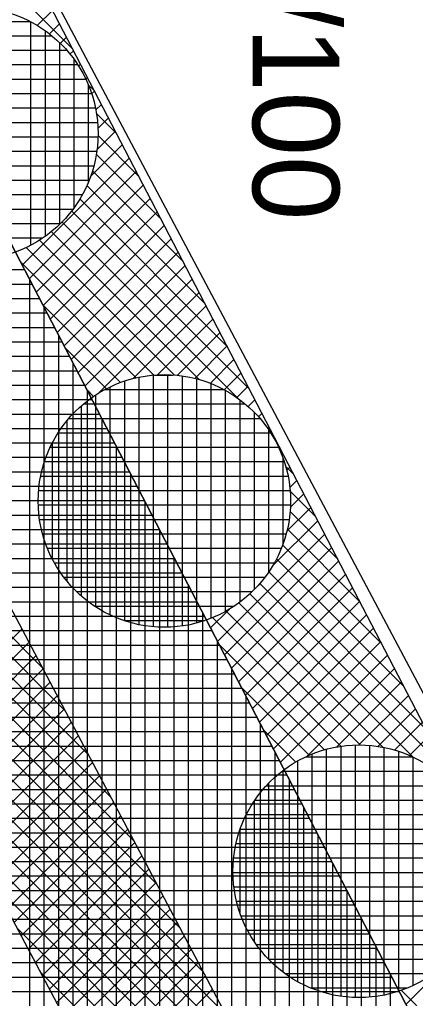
# Model space of a CAD drawing. Extents: x -565346 to -564154, y -1097386 to -1095620.
# Drawn here: x -564305.27 to -564299.78, y -1096071.21 to -1096057.65 of the extents above; entities that cross this region are included whole.
import ezdxf

# ---------------------------------------------------------------- set-up
doc = ezdxf.new("R2010")
doc.units = 0
for name, color, linetype in [('Vrstva 13', 7, 'Continuous'), ('Vrstva 40', 7, 'Continuous'), ('Vrstva 41', 7, 'Continuous'), ('Vrstva 42', 7, 'Continuous'), ('Vrstva 43', 7, 'Continuous'), ('Vrstva 44', 7, 'Continuous')]:
    doc.layers.add(name, color=color, linetype=linetype)

msp = doc.modelspace()

# ---------------------------------------------------------------- linework, layer by layer
at = {"layer": 'Vrstva 13'}
msp.add_line((-564310.36, -1096046.86), (-564292.41, -1096080.67), dxfattribs=at)
at = {"layer": 'Vrstva 41'}
msp.add_lwpolyline([(-564317.9, -1095918.68), (-564319.837, -1095918.359), (-564322.792, -1095953.471), (-564316.779, -1095990.732), (-564317.708, -1096006.365), (-564312.296, -1096047.478), (-564277.924, -1096113.563), (-564240.773, -1096165.119), (-564207.452, -1096208.029), (-564205.9, -1096206.84), (-564239.15, -1096163.95), (-564276.21, -1096112.52), (-564310.36, -1096046.86), (-564315.7, -1096006.29), (-564314.77, -1095990.63), (-564320.6, -1095954.5), (-564320.51, -1095950.21)], close=True, dxfattribs=at)
at = {"layer": 'Vrstva 42'}
for p, q in [((-564307.288, -1096055.299), (-564304.543, -1096058.045)), ((-564304.816, -1096057.519), (-564305.027, -1096057.729)), ((-564304.72, -1096057.705), (-564304.86, -1096057.845)), ((-564304.623, -1096057.891), (-564304.71, -1096057.977)), ((-564304.526, -1096058.077), (-564304.575, -1096058.126)), ((-564304.429, -1096058.263), (-564304.456, -1096058.29)), ((-564304.333, -1096058.449), (-564304.355, -1096058.472)), ((-564304.321, -1096058.55), (-564304.236, -1096058.634)), ((-564304.236, -1096058.635), (-564304.274, -1096058.673)), ((-564304.139, -1096058.821), (-564304.216, -1096058.898)), ((-564304.209, -1096058.944), (-564303.93, -1096059.223)), ((-564304.042, -1096059.007), (-564304.188, -1096059.153)), ((-564303.945, -1096059.193), (-564304.2, -1096059.448)), ((-564304.185, -1096059.251), (-564303.623, -1096059.813)), ((-564303.849, -1096059.379), (-564304.292, -1096059.823)), ((-564303.752, -1096059.565), (-564305.237, -1096061.05)), ((-564304.21, -1096059.509), (-564303.317, -1096060.402)), ((-564304.263, -1096059.739), (-564303.01, -1096060.992)), ((-564303.655, -1096059.751), (-564305.14, -1096061.236)), ((-564303.558, -1096059.938), (-564305.043, -1096061.422)), ((-564304.34, -1096059.945), (-564302.704, -1096061.581)), ((-564303.462, -1096060.124), (-564304.946, -1096061.608)), ((-564304.438, -1096060.13), (-564302.397, -1096062.17)), ((-564303.365, -1096060.31), (-564304.85, -1096061.795)), ((-564304.554, -1096060.297), (-564302.091, -1096062.76)), ((-564303.268, -1096060.496), (-564304.753, -1096061.981)), ((-564304.686, -1096060.447), (-564302.235, -1096062.898)), ((-564304.834, -1096060.582), (-564302.782, -1096062.634)), ((-564303.171, -1096060.682), (-564304.656, -1096062.167)), ((-564305.18, -1096060.802), (-564303.41, -1096062.572)), ((-564304.998, -1096060.701), (-564303.127, -1096062.571)), ((-564303.074, -1096060.868), (-564304.559, -1096062.353)), ((-564305.261, -1096061.003), (-564303.655, -1096062.609)), ((-564302.978, -1096061.054), (-564304.463, -1096062.539)), ((-564302.881, -1096061.24), (-564304.366, -1096062.725)), ((-564302.784, -1096061.426), (-564304.188, -1096062.83)), ((-564304.955, -1096061.592), (-564303.872, -1096062.675)), ((-564302.687, -1096061.612), (-564303.696, -1096062.62)), ((-564309.792, -1096061.789), (-564304.965, -1096066.616)), ((-564302.591, -1096061.798), (-564303.362, -1096062.569)), ((-564302.494, -1096061.984), (-564303.083, -1096062.574)), ((-564304.648, -1096062.182), (-564304.068, -1096062.762)), ((-564302.397, -1096062.17), (-564302.844, -1096062.617)), ((-564309.472, -1096062.392), (-564304.645, -1096067.218)), ((-564302.3, -1096062.356), (-564302.629, -1096062.686)), ((-564302.203, -1096062.542), (-564302.435, -1096062.774)), ((-564304.342, -1096062.771), (-564304.246, -1096062.867)), ((-564302.107, -1096062.729), (-564302.26, -1096062.882)), ((-564309.152, -1096062.995), (-564304.325, -1096067.821)), ((-564302.01, -1096062.915), (-564302.102, -1096063.007)), ((-564301.913, -1096063.101), (-564301.96, -1096063.148)), ((-564301.848, -1096063.285), (-564301.784, -1096063.349)), ((-564301.816, -1096063.287), (-564301.835, -1096063.305)), ((-564301.72, -1096063.473), (-564301.727, -1096063.48)), ((-564308.832, -1096063.598), (-564304.005, -1096068.424)), ((-564301.623, -1096063.659), (-564301.638, -1096063.674)), ((-564301.584, -1096063.832), (-564301.477, -1096063.938)), ((-564301.526, -1096063.845), (-564301.569, -1096063.888)), ((-564301.429, -1096064.031), (-564301.525, -1096064.126)), ((-564308.512, -1096064.201), (-564303.685, -1096069.027)), ((-564301.521, -1096064.177), (-564301.171, -1096064.528)), ((-564301.333, -1096064.217), (-564301.519, -1096064.403)), ((-564301.236, -1096064.403), (-564301.567, -1096064.735)), ((-564301.522, -1096064.46), (-564300.864, -1096065.117)), ((-564301.139, -1096064.589), (-564301.765, -1096065.215)), ((-564301.559, -1096064.705), (-564300.558, -1096065.707)), ((-564308.192, -1096064.804), (-564303.365, -1096069.63)), ((-564301.042, -1096064.775), (-564302.527, -1096066.26)), ((-564300.945, -1096064.961), (-564302.43, -1096066.446)), ((-564301.625, -1096064.922), (-564300.251, -1096066.296)), ((-564300.849, -1096065.147), (-564302.334, -1096066.632)), ((-564301.712, -1096065.118), (-564299.945, -1096066.885)), ((-564301.817, -1096065.296), (-564299.638, -1096067.475)), ((-564307.872, -1096065.407), (-564303.045, -1096070.233)), ((-564300.752, -1096065.333), (-564302.237, -1096066.818)), ((-564300.655, -1096065.52), (-564302.14, -1096067.004)), ((-564301.94, -1096065.456), (-564299.332, -1096068.064)), ((-564302.079, -1096065.6), (-564299.815, -1096067.864)), ((-564300.558, -1096065.706), (-564302.043, -1096067.19)), ((-564302.363, -1096065.813), (-564302.624, -1096066.074)), ((-564302.406, -1096065.839), (-564300.55, -1096067.695)), ((-564302.233, -1096065.728), (-564300.235, -1096067.727)), ((-564302.597, -1096065.93), (-564300.813, -1096067.714)), ((-564300.462, -1096065.892), (-564301.946, -1096067.377)), ((-564307.551, -1096066.009), (-564302.725, -1096070.836)), ((-564305.244, -1096066.091), (-564306.723, -1096067.57)), ((-564300.365, -1096066.078), (-564301.85, -1096067.563)), ((-564305.146, -1096066.275), (-564306.625, -1096067.754)), ((-564302.502, -1096066.308), (-564301.046, -1096067.764)), ((-564300.268, -1096066.264), (-564301.753, -1096067.749)), ((-564305.048, -1096066.46), (-564306.527, -1096067.939)), ((-564300.171, -1096066.45), (-564301.656, -1096067.935)), ((-564307.231, -1096066.612), (-564302.405, -1096071.439)), ((-564304.95, -1096066.645), (-564306.429, -1096068.124)), ((-564300.074, -1096066.636), (-564301.291, -1096067.853)), ((-564304.852, -1096066.83), (-564306.331, -1096068.309)), ((-564302.196, -1096066.897), (-564301.256, -1096067.837)), ((-564299.978, -1096066.822), (-564300.88, -1096067.725)), ((-564304.754, -1096067.014), (-564306.233, -1096068.493)), ((-564299.881, -1096067.008), (-564300.567, -1096067.694)), ((-564304.656, -1096067.199), (-564306.135, -1096068.678)), ((-564299.784, -1096067.194), (-564300.306, -1096067.716)), ((-564306.911, -1096067.215), (-564302.085, -1096072.042)), ((-564304.558, -1096067.384), (-564306.037, -1096068.863)), ((-564299.687, -1096067.38), (-564300.073, -1096067.766)), ((-564304.459, -1096067.569), (-564305.938, -1096069.048)), ((-564301.889, -1096067.486), (-564301.444, -1096067.931)), ((-564299.591, -1096067.566), (-564299.865, -1096067.84)), ((-564306.591, -1096067.818), (-564301.765, -1096072.645)), ((-564304.361, -1096067.753), (-564305.84, -1096069.232)), ((-564304.263, -1096067.938), (-564305.742, -1096069.417)), ((-564304.165, -1096068.123), (-564305.644, -1096069.602)), ((-564306.271, -1096068.421), (-564301.445, -1096073.248)), ((-564304.067, -1096068.308), (-564305.546, -1096069.787)), ((-564303.969, -1096068.492), (-564305.448, -1096069.972)), ((-564303.871, -1096068.677), (-564305.35, -1096070.156)), ((-564303.773, -1096068.862), (-564305.252, -1096070.341)), ((-564305.951, -1096069.024), (-564301.124, -1096073.851)), ((-564303.675, -1096069.047), (-564305.154, -1096070.526)), ((-564303.577, -1096069.232), (-564305.056, -1096070.711)), ((-564303.479, -1096069.416), (-564304.958, -1096070.895)), ((-564305.631, -1096069.627), (-564300.804, -1096074.454)), ((-564303.381, -1096069.601), (-564304.86, -1096071.08)), ((-564303.282, -1096069.786), (-564304.761, -1096071.265)), ((-564298.429, -1096069.799), (-564299.914, -1096071.284)), ((-564303.184, -1096069.971), (-564304.663, -1096071.45)), ((-564303.086, -1096070.155), (-564304.565, -1096071.634)), ((-564305.311, -1096070.23), (-564300.484, -1096075.057)), ((-564302.988, -1096070.34), (-564304.467, -1096071.819)), ((-564302.89, -1096070.525), (-564304.369, -1096072.004)), ((-564302.792, -1096070.71), (-564304.271, -1096072.189)), ((-564304.991, -1096070.833), (-564300.164, -1096075.659)), ((-564302.694, -1096070.894), (-564304.173, -1096072.373)), ((-564302.596, -1096071.079), (-564304.075, -1096072.558)), ((-564299.981, -1096071.092), (-564298.238, -1096072.834))]:
    msp.add_line(p, q, dxfattribs=at)
msp.add_lwpolyline([(-564322.318, -1095918.024), (-564324.311, -1095917.856), (-564327.322, -1095953.642), (-564321.3, -1095990.958), (-564322.226, -1096006.529), (-564316.652, -1096048.867), (-564298.213, -1096083.6), (-564281.777, -1096115.914), (-564244.285, -1096167.937), (-564211.109, -1096210.658), (-564209.483, -1096209.49), (-564242.801, -1096166.581), (-564280.063, -1096114.871), (-564296.384, -1096082.78), (-564314.716, -1096048.249), (-564320.218, -1096006.455), (-564319.291, -1095990.856), (-564325.309, -1095953.567)], close=True, dxfattribs=at)
at = {"layer": 'Vrstva 43'}
for p, q in [((-564313.105, -1096061.11), (-564305.206, -1096061.11)), ((-564313.001, -1096061.31), (-564305.102, -1096061.31)), ((-564305.13, -1096076.441), (-564305.13, -1096061.256)), ((-564312.897, -1096061.51), (-564304.998, -1096061.51)), ((-564304.93, -1096076.825), (-564304.93, -1096061.64)), ((-564312.793, -1096061.71), (-564304.894, -1096061.71)), ((-564312.689, -1096061.91), (-564304.79, -1096061.91)), ((-564304.73, -1096077.21), (-564304.73, -1096062.025)), ((-564312.585, -1096062.11), (-564304.686, -1096062.11)), ((-564312.481, -1096062.31), (-564304.582, -1096062.31)), ((-564304.53, -1096077.594), (-564304.53, -1096062.409)), ((-564312.377, -1096062.51), (-564304.478, -1096062.51)), ((-564312.273, -1096062.71), (-564304.374, -1096062.71)), ((-564304.33, -1096077.979), (-564304.33, -1096062.794)), ((-564312.169, -1096062.91), (-564304.27, -1096062.91)), ((-564312.065, -1096063.11), (-564304.166, -1096063.11)), ((-564304.13, -1096078.363), (-564304.13, -1096063.178)), ((-564311.96, -1096063.31), (-564304.061, -1096063.31)), ((-564311.856, -1096063.51), (-564303.957, -1096063.51)), ((-564303.93, -1096078.748), (-564303.93, -1096063.563)), ((-564311.752, -1096063.71), (-564303.853, -1096063.71)), ((-564311.648, -1096063.91), (-564303.749, -1096063.91)), ((-564303.73, -1096079.132), (-564303.73, -1096063.947)), ((-564311.544, -1096064.11), (-564303.645, -1096064.11)), ((-564311.44, -1096064.31), (-564303.541, -1096064.31)), ((-564303.53, -1096079.517), (-564303.53, -1096064.332)), ((-564311.336, -1096064.51), (-564303.437, -1096064.51)), ((-564311.232, -1096064.71), (-564303.333, -1096064.71)), ((-564303.33, -1096079.901), (-564303.33, -1096064.716)), ((-564311.128, -1096064.91), (-564303.229, -1096064.91)), ((-564311.024, -1096065.11), (-564303.125, -1096065.11)), ((-564303.13, -1096080.285), (-564303.13, -1096065.101)), ((-564310.92, -1096065.31), (-564303.021, -1096065.31)), ((-564310.816, -1096065.51), (-564302.917, -1096065.51)), ((-564302.93, -1096080.67), (-564302.93, -1096065.485)), ((-564310.712, -1096065.71), (-564302.813, -1096065.71)), ((-564310.608, -1096065.91), (-564302.709, -1096065.91)), ((-564302.73, -1096081.054), (-564302.73, -1096065.87)), ((-564310.504, -1096066.11), (-564302.605, -1096066.11)), ((-564310.4, -1096066.31), (-564302.501, -1096066.31)), ((-564302.53, -1096081.439), (-564302.53, -1096066.255)), ((-564310.296, -1096066.51), (-564302.397, -1096066.51)), ((-564302.33, -1096081.823), (-564302.33, -1096066.639)), ((-564310.192, -1096066.71), (-564302.293, -1096066.71)), ((-564310.088, -1096066.91), (-564302.189, -1096066.91)), ((-564302.13, -1096082.208), (-564302.13, -1096067.024)), ((-564309.984, -1096067.11), (-564302.085, -1096067.11)), ((-564309.88, -1096067.31), (-564301.981, -1096067.31)), ((-564301.93, -1096082.592), (-564301.93, -1096067.408)), ((-564309.776, -1096067.51), (-564301.877, -1096067.51)), ((-564309.672, -1096067.71), (-564301.773, -1096067.71)), ((-564301.73, -1096082.977), (-564301.73, -1096067.793)), ((-564309.568, -1096067.91), (-564301.669, -1096067.91)), ((-564309.464, -1096068.11), (-564301.565, -1096068.11)), ((-564301.53, -1096083.361), (-564301.53, -1096068.177)), ((-564309.36, -1096068.31), (-564301.461, -1096068.31)), ((-564309.255, -1096068.51), (-564301.357, -1096068.51)), ((-564301.33, -1096083.746), (-564301.33, -1096068.562)), ((-564309.151, -1096068.71), (-564301.253, -1096068.71)), ((-564309.047, -1096068.91), (-564301.149, -1096068.91)), ((-564301.13, -1096084.13), (-564301.13, -1096068.946)), ((-564308.943, -1096069.11), (-564301.045, -1096069.11)), ((-564308.839, -1096069.31), (-564300.941, -1096069.31)), ((-564300.93, -1096084.515), (-564300.93, -1096069.331)), ((-564308.735, -1096069.51), (-564300.837, -1096069.51)), ((-564308.631, -1096069.71), (-564300.733, -1096069.71)), ((-564300.73, -1096084.899), (-564300.73, -1096069.715)), ((-564308.527, -1096069.91), (-564300.629, -1096069.91)), ((-564308.423, -1096070.11), (-564300.525, -1096070.11)), ((-564300.53, -1096085.284), (-564300.53, -1096070.1)), ((-564308.319, -1096070.31), (-564300.421, -1096070.31)), ((-564308.215, -1096070.51), (-564300.317, -1096070.51)), ((-564300.33, -1096085.668), (-564300.33, -1096070.484)), ((-564308.111, -1096070.71), (-564300.213, -1096070.71)), ((-564308.007, -1096070.91), (-564300.109, -1096070.91)), ((-564300.13, -1096086.053), (-564300.13, -1096070.869)), ((-564307.903, -1096071.11), (-564300.005, -1096071.11))]:
    msp.add_line(p, q, dxfattribs=at)
msp.add_lwpolyline([(-564173.087, -1096301.985), (-564179.49, -1096264.63), (-564192.762, -1096228.697), (-564195.888, -1096224.348), (-564194.264, -1096223.181), (-564206.02, -1096206.88), (-564207.452, -1096208.029), (-564240.773, -1096165.119), (-564277.924, -1096113.563), (-564312.296, -1096047.478), (-564317.708, -1096006.365)], dxfattribs=at)
at = {"layer": 'Vrstva 44'}
for p, q in [((-564306.737, -1096057.67), (-564305.132, -1096057.67)), ((-564305.12, -1096057.676), (-564305.12, -1096060.771)), ((-564304.92, -1096057.8), (-564304.92, -1096060.648)), ((-564307.04, -1096057.87), (-564304.826, -1096057.87)), ((-564304.72, -1096057.965), (-564304.72, -1096060.482)), ((-564307.249, -1096058.07), (-564304.621, -1096058.07)), ((-564304.52, -1096058.196), (-564304.52, -1096060.253)), ((-564307.399, -1096058.27), (-564304.469, -1096058.27)), ((-564307.513, -1096058.47), (-564304.357, -1096058.47)), ((-564304.32, -1096058.551), (-564304.32, -1096059.895)), ((-564307.593, -1096058.67), (-564304.275, -1096058.67)), ((-564307.646, -1096058.87), (-564304.221, -1096058.87)), ((-564307.676, -1096059.07), (-564304.193, -1096059.07)), ((-564307.683, -1096059.27), (-564304.187, -1096059.27)), ((-564307.666, -1096059.47), (-564304.203, -1096059.47)), ((-564307.625, -1096059.67), (-564304.242, -1096059.67)), ((-564307.559, -1096059.87), (-564304.309, -1096059.87)), ((-564307.465, -1096060.07), (-564304.405, -1096060.07)), ((-564307.335, -1096060.27), (-564304.531, -1096060.27)), ((-564307.162, -1096060.47), (-564304.708, -1096060.47)), ((-564306.917, -1096060.67), (-564304.952, -1096060.67)), ((-564303.42, -1096062.572), (-564303.42, -1096066.056)), ((-564303.404, -1096062.57), (-564303.151, -1096062.57)), ((-564303.22, -1096062.566), (-564303.22, -1096066.062)), ((-564303.02, -1096062.583), (-564303.02, -1096066.046)), ((-564303.82, -1096062.657), (-564303.82, -1096065.972)), ((-564303.62, -1096062.602), (-564303.62, -1096066.027)), ((-564302.82, -1096062.624), (-564302.82, -1096066.007)), ((-564302.62, -1096062.689), (-564302.62, -1096065.94)), ((-564304.22, -1096062.85), (-564304.22, -1096065.78)), ((-564304.085, -1096062.77), (-564302.442, -1096062.77)), ((-564304.02, -1096062.737), (-564304.02, -1096065.891)), ((-564302.42, -1096062.783), (-564302.42, -1096065.845)), ((-564304.382, -1096062.97), (-564302.145, -1096062.97)), ((-564302.22, -1096062.913), (-564302.22, -1096065.718)), ((-564304.42, -1096063.002), (-564304.42, -1096065.626)), ((-564302.02, -1096063.085), (-564302.02, -1096065.542)), ((-564304.62, -1096063.21), (-564304.62, -1096065.419)), ((-564304.588, -1096063.17), (-564301.942, -1096063.17)), ((-564304.736, -1096063.37), (-564301.793, -1096063.37)), ((-564301.82, -1096063.327), (-564301.82, -1096065.298)), ((-564304.82, -1096063.516), (-564304.82, -1096065.112)), ((-564304.848, -1096063.57), (-564301.683, -1096063.57)), ((-564304.926, -1096063.77), (-564301.602, -1096063.77)), ((-564301.62, -1096063.722), (-564301.62, -1096064.91)), ((-564304.978, -1096063.97), (-564301.55, -1096063.97)), ((-564305.007, -1096064.17), (-564301.523, -1096064.17)), ((-564305.013, -1096064.37), (-564301.517, -1096064.37)), ((-564304.995, -1096064.57), (-564301.535, -1096064.57)), ((-564304.952, -1096064.77), (-564301.575, -1096064.77)), ((-564304.885, -1096064.97), (-564301.644, -1096064.97)), ((-564304.79, -1096065.17), (-564301.74, -1096065.17)), ((-564304.658, -1096065.37), (-564301.869, -1096065.37)), ((-564304.483, -1096065.57), (-564302.048, -1096065.57)), ((-564304.234, -1096065.77), (-564302.297, -1096065.77)), ((-564303.825, -1096065.97), (-564302.703, -1096065.97)), ((-564300.82, -1096067.715), (-564300.82, -1096071.175)), ((-564300.62, -1096067.697), (-564300.62, -1096071.194)), ((-564300.42, -1096067.702), (-564300.42, -1096071.187)), ((-564300.22, -1096067.73), (-564300.22, -1096071.158)), ((-564301.304, -1096067.86), (-564299.827, -1096067.86)), ((-564301.22, -1096067.823), (-564301.22, -1096071.067)), ((-564301.02, -1096067.755), (-564301.02, -1096071.134)), ((-564300.02, -1096067.783), (-564300.02, -1096071.105)), ((-564299.82, -1096067.863), (-564299.82, -1096071.027)), ((-564301.42, -1096067.92), (-564301.42, -1096070.97)), ((-564301.635, -1096068.06), (-564299.498, -1096068.06)), ((-564301.62, -1096068.049), (-564301.62, -1096070.839)), ((-564301.852, -1096068.26), (-564299.28, -1096068.26)), ((-564301.82, -1096068.228), (-564301.82, -1096070.662)), ((-564302.02, -1096068.475), (-564302.02, -1096070.415)), ((-564302.01, -1096068.46), (-564299.119, -1096068.46)), ((-564302.128, -1096068.66), (-564299.003, -1096068.66)), ((-564302.22, -1096068.877), (-564302.22, -1096070.014)), ((-564302.215, -1096068.86), (-564298.918, -1096068.86)), ((-564302.271, -1096069.06), (-564298.858, -1096069.06)), ((-564302.304, -1096069.26), (-564298.826, -1096069.26)), ((-564302.313, -1096069.46), (-564298.817, -1096069.46)), ((-564302.301, -1096069.66), (-564298.831, -1096069.66)), ((-564302.265, -1096069.86), (-564298.867, -1096069.86)), ((-564302.202, -1096070.06), (-564298.927, -1096070.06)), ((-564302.112, -1096070.26), (-564299.019, -1096070.26)), ((-564301.99, -1096070.46), (-564299.142, -1096070.46)), ((-564301.822, -1096070.66), (-564299.309, -1096070.66)), ((-564301.591, -1096070.86), (-564299.538, -1096070.86)), ((-564301.236, -1096071.06), (-564299.897, -1096071.06))]:
    msp.add_line(p, q, dxfattribs=at)
for centre in [(-564305.934, -1096059.224), (-564303.265, -1096064.314), (-564300.565, -1096069.445)]:
    msp.add_circle(centre, 1.75, dxfattribs=at)

# ---------------------------------------------------------------- texts
at = {"layer": 'Vrstva 40'}
msp.add_text('18/100', height=1.2, rotation=270, dxfattribs=at).set_placement((-564302.04, -1096055.52))

doc.saveas('drawing.dxf')
